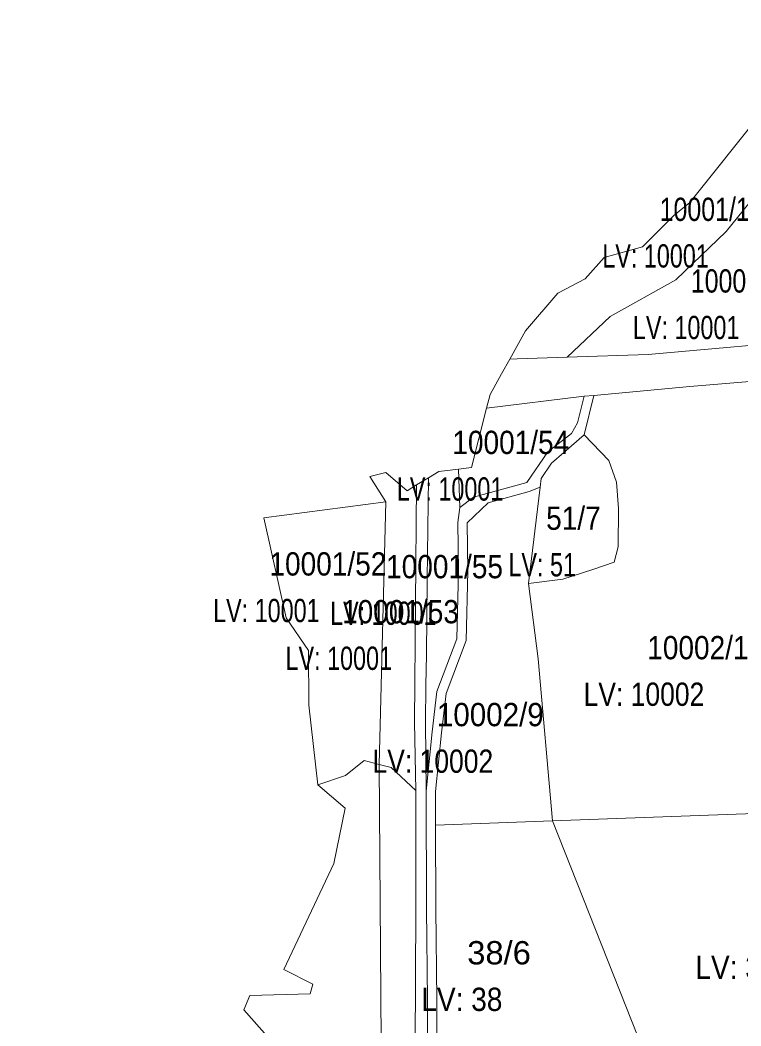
# Model space of a CAD drawing. Extents: x -713758 to -711119, y -1123067 to -1120789.
# Drawn here: x -713099.1 to -712789.6, y -1121945 to -1121513.2 of the extents above; entities that cross this region are included whole.
import ezdxf
from ezdxf.enums import TextEntityAlignment as Align

# ---------------------------------------------------------------- set-up
doc = ezdxf.new("R2010")
doc.units = 0
doc.header["$LTSCALE"] = 4
doc.layers.add('10', color=7, linetype='Continuous', lineweight=13)
doc.layers.add('11', color=7, linetype='Continuous')
doc.layers.add('13', color=7, linetype='Continuous')

msp = doc.modelspace()

# ---------------------------------------------------------------- linework, layer by layer
at = {"layer": '10'}
for points in [[(-712888.87, -1121658.79), (-712885.65, -1121658.68), (-712864.22, -1121657.94), (-712845.67, -1121640.48), (-712817.6, -1121624.66), (-712795.86, -1121603.97), (-712752.88, -1121550.69), (-712750.3, -1121538.21), (-712744.77, -1121513.2), (-712749.34, -1121513.8), (-712811.48, -1121591.48), (-712818.41, -1121597.09), (-712831.79, -1121610.57), (-712848.31, -1121615.15), (-712856.5, -1121624.23), (-712868.15, -1121630.5), (-712882.05, -1121646.55)], [(-712864.22, -1121657.94), (-712829.35, -1121656.74), (-712752.3, -1121649.86), (-712747.43, -1121645.94), (-712745.02, -1121640.69), (-712743.67, -1121625.84), (-712749.88, -1121594.58), (-712754.14, -1121574.84), (-712754.67, -1121564.53), (-712752.88, -1121550.69), (-712795.86, -1121603.97), (-712817.6, -1121624.66), (-712845.67, -1121640.48)], [(-712880.84, -1121755.13), (-712866.01, -1121753.2), (-712853.12, -1121749.15), (-712844, -1121745.94), (-712842.34, -1121739.38), (-712842.12, -1121722.83), (-712842.97, -1121711.59), (-712846.26, -1121702.25), (-712856.88, -1121691.21), (-712852.69, -1121674.34), (-712811.56, -1121670.57), (-712756.64, -1121665.93), (-712748.52, -1121666.41), (-712740.68, -1121669.42), (-712734.88, -1121675.75), (-712731.11, -1121683.63), (-712727.43, -1121700.1), (-712722.81, -1121723.55), (-712713.57, -1121776.81), (-712703.43, -1121836.37), (-712700.91, -1121850.47), (-712700.85, -1121850.86), (-712870.42, -1121857.05), (-712876.71, -1121787.4)], [(-712910.92, -1121705.99), (-712910.25, -1121722.4), (-712904.42, -1121718.05), (-712881.55, -1121711.7), (-712872.51, -1121698.58), (-712862.4, -1121690.66), (-712859.74, -1121686.14), (-712856.91, -1121674.73), (-712898.77, -1121679.75), (-712905.27, -1121705.33)], [(-712880.84, -1121755.13), (-712866.01, -1121753.2), (-712853.12, -1121749.15), (-712844, -1121745.94), (-712842.34, -1121739.38), (-712842.12, -1121722.83), (-712842.97, -1121711.59), (-712846.26, -1121702.25), (-712856.88, -1121691.21), (-712865.68, -1121698.81), (-712870.89, -1121703.37), (-712875.37, -1121709.98), (-712875.83, -1121713.75)], [(-712925.09, -1121814.71), (-712924.79, -1121844.26), (-712922.09, -1121818.84), (-712920.1, -1121801.42), (-712911.58, -1121778.81), (-712910.91, -1121749.85), (-712911.11, -1121728.85), (-712910.25, -1121722.4), (-712910.92, -1121705.99), (-712919.34, -1121706.96), (-712923.79, -1121709.7), (-712924.31, -1121753.2), (-712924.55, -1121785.57), (-712924.92, -1121798.83)], [(-712948.99, -1121709.09), (-712942.02, -1121720.04), (-712944.91, -1121832.77), (-712939.8, -1121834.06), (-712929.12, -1121844.01), (-712929.69, -1121814.71), (-712928.84, -1121712.8), (-712932.86, -1121715.27), (-712942.02, -1121707.43)], [(-712920.79, -1121844.47), (-712918.11, -1121819.22), (-712916.18, -1121802.37), (-712907.6, -1121779.58), (-712906.91, -1121749.87), (-712907.11, -1121729.1), (-712898.12, -1121720.45), (-712880.48, -1121715.55), (-712875.83, -1121713.75), (-712880.84, -1121755.13), (-712876.71, -1121787.4), (-712870.42, -1121857.05), (-712920.74, -1121858.89)], [(-712994.4, -1121726.84), (-712984.83, -1121769.81), (-712975.22, -1121783.85), (-712975.15, -1121807.4), (-712971.24, -1121841.48), (-712959.38, -1121837.47), (-712951.29, -1121831.16), (-712944.91, -1121832.77), (-712942.02, -1121720.04)], [(-713099.09, -1122050.28), (-713093.3, -1122058.22), (-713092.2, -1122062.07), (-713078.09, -1122058.85), (-713040.02, -1122048.87), (-712992.26, -1122035.27), (-712984.65, -1122032.69), (-712954.71, -1122007.7), (-712941.79, -1121993.69), (-712936.86, -1121985.6), (-712931.35, -1121968.92), (-712929.46, -1121954.09), (-712929.21, -1121894.95), (-712929.12, -1121844.01), (-712939.8, -1121834.06), (-712944.91, -1121832.77), (-712944, -1121951.73), (-712945.8, -1121967.3), (-712957.4, -1121986.04), (-712977.36, -1122008.49), (-712996.6, -1122018.99), (-713045.48, -1122033.25), (-713082.19, -1122044)], [(-712870.42, -1121857.05), (-712700.85, -1121850.86), (-712698.93, -1121864.01), (-712694.13, -1121895.03), (-712687.55, -1121951.31), (-712831.1, -1121956.54)], [(-712920.74, -1121858.89), (-712870.42, -1121857.05), (-712831.1, -1121956.54), (-712918.75, -1121959.74), (-712920.13, -1121953.58), (-712920.19, -1121933.95), (-712920.62, -1121894.76)]]:
    msp.add_lwpolyline(points, close=True, dxfattribs=at)
for points in [[(-712756.64, -1121665.93), (-712811.56, -1121670.57), (-712852.69, -1121674.34), (-712856.91, -1121674.73), (-712898.77, -1121679.75), (-712897.28, -1121673.89), (-712892.39, -1121665.12), (-712888.87, -1121658.79), (-712885.65, -1121658.68), (-712864.22, -1121657.94), (-712829.35, -1121656.74), (-712752.3, -1121649.86)], [(-712865.68, -1121698.81), (-712856.88, -1121691.21), (-712852.69, -1121674.34), (-712856.91, -1121674.73), (-712859.74, -1121686.14), (-712862.4, -1121690.66), (-712872.51, -1121698.58), (-712881.55, -1121711.7), (-712904.42, -1121718.05), (-712910.25, -1121722.4), (-712911.11, -1121728.85), (-712910.91, -1121749.85), (-712911.58, -1121778.81), (-712920.1, -1121801.42), (-712922.09, -1121818.84), (-712924.79, -1121844.26), (-712924.62, -1121894.82), (-712924.19, -1121934.01), (-712924.13, -1121954.03)], [(-712920.13, -1121953.58), (-712920.19, -1121933.95), (-712920.62, -1121894.76), (-712920.74, -1121858.89), (-712920.79, -1121844.47), (-712918.11, -1121819.22), (-712916.18, -1121802.37), (-712907.6, -1121779.58), (-712906.91, -1121749.87), (-712907.11, -1121729.1), (-712898.12, -1121720.45), (-712880.48, -1121715.55), (-712875.83, -1121713.75), (-712875.37, -1121709.98), (-712870.89, -1121703.37), (-712865.68, -1121698.81)], [(-712924.13, -1121954.03), (-712924.19, -1121934.01), (-712924.62, -1121894.82), (-712924.79, -1121844.26), (-712925.09, -1121814.71), (-712924.92, -1121798.83), (-712924.55, -1121785.57), (-712924.31, -1121753.2), (-712923.79, -1121709.7), (-712928.84, -1121712.8), (-712929.69, -1121814.71), (-712929.12, -1121844.01), (-712929.21, -1121894.95), (-712929.46, -1121954.09)], [(-712991.96, -1121950.64), (-713003.08, -1121938.2), (-713000.42, -1121932.06), (-712974.54, -1121931.23), (-712973.38, -1121927.09), (-712985.81, -1121920.81), (-712964.42, -1121875.32), (-712959.53, -1121851.63), (-712971.24, -1121841.48), (-712959.38, -1121837.47), (-712951.29, -1121831.16), (-712944.91, -1121832.77), (-712944, -1121951.73)]]:
    msp.add_lwpolyline(points, dxfattribs=at)

# ---------------------------------------------------------------- texts
at = {"layer": '11'}
for s, width, p in [('10001/14', 0.8, (-712802.16, -1121599.44)), ('10001/15', 0.8, (-712788.78, -1121630.19)), ('10001/54', 0.9, (-712888.4, -1121699.51)), ('51/7', 0.9, (-712861.5, -1121732.05)), ('10001/52', 0.9, (-712966.929, -1121751.69)), ('10001/55', 0.9, (-712916.84, -1121752.86)), ('10001/53', 0.9, (-712935.76, -1121772.2)), ('10002/10', 0.9, (-712804.71, -1121787.64)), ('10002/9', 0.95, (-712897.191, -1121816.39)), ('38/6', 1.05, (-712893.44, -1121918.64))]:
    msp.add_text(s, height=10, dxfattribs=dict(at, width=width)).set_placement(p, align=Align.CENTER)
at = {"layer": '13'}
for s, width, p in [('LV: 10001 ', 0.75, (-712824.846, -1121619.44)), ('LV: 10001 ', 0.75, (-712811.7, -1121650.19)), ('LV: 10001 ', 0.75, (-712913.06, -1121719.51)), ('LV: 51 ', 0.75, (-712873.512, -1121752.05)), ('LV: 10001 ', 0.75, (-712991.958, -1121771.69)), ('LV: 10001 ', 0.75, (-712941.734, -1121772.86)), ('LV: 10001 ', 0.75, (-712960.856, -1121792.2)), ('LV: 10002 ', 0.85, (-712829.638, -1121807.64)), ('LV: 10002 ', 0.85, (-712920.278, -1121836.39)), ('LV: 38 ', 0.9, (-712790.057, -1121924.89)), ('LV: 38 ', 0.9, (-712907.728, -1121938.64))]:
    msp.add_text(s, height=10, dxfattribs=dict(at, width=width)).set_placement(p, align=Align.CENTER)

doc.saveas('drawing.dxf')
